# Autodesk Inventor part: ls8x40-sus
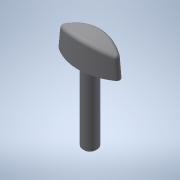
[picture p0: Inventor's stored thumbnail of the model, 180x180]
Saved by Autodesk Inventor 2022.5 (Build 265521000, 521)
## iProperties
Created: 2016-12
Part Number: ls8x40-sus
Material: 一般
Document SubType Name: Modeling
Designer: imaocorp
Density: 1 g/cm^3
Appearance: 既定
Author: imaocorp
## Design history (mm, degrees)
node "ls8x40-sus.x_t1"
node "ls8x40-sus"
node "Base1"
